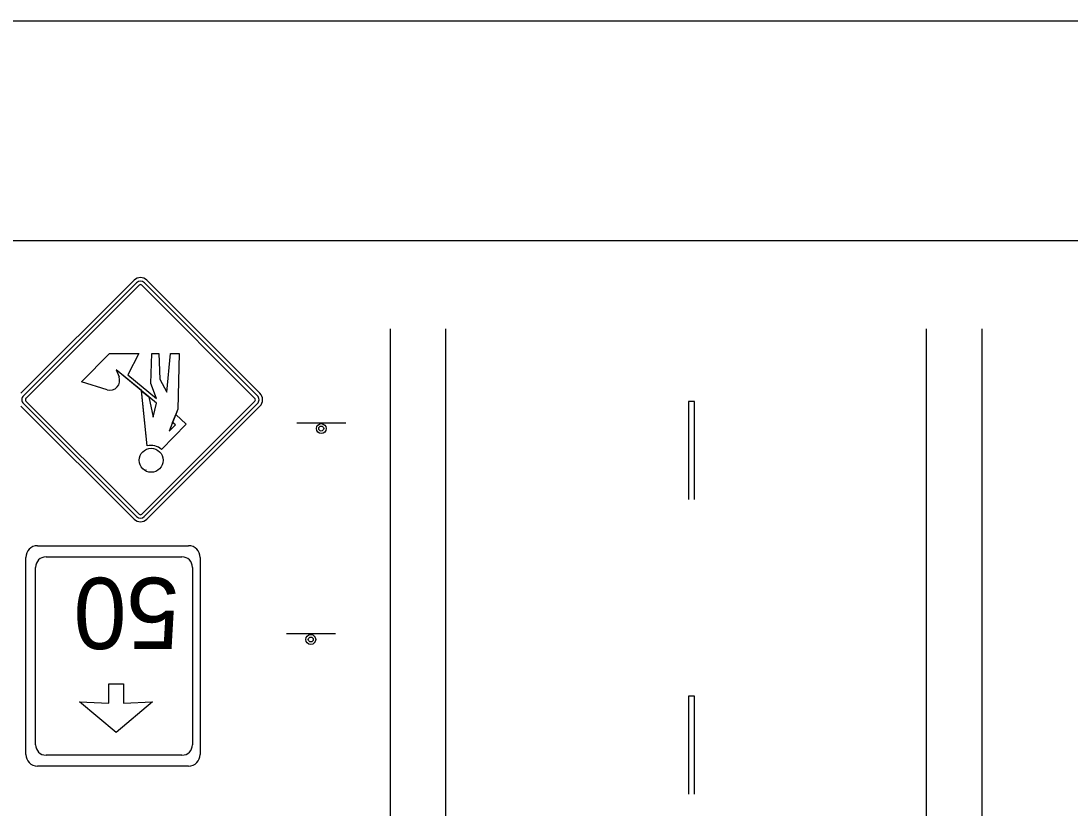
# Model space of a CAD drawing. Extents: x 2195 to 2411, y 202 to 481.
# Drawn here: x 2247.9 to 2299.6, y 442.1 to 480.9 of the extents above; entities that cross this region are included whole.
import ezdxf

# ---------------------------------------------------------------- set-up
doc = ezdxf.new("R2010")
doc.units = 0
for name, color, linetype in [('Level 1', 7, 'Continuous'), ('Level 10', 7, 'Continuous'), ('Level 2', 7, 'Continuous'), ('Level 44', 7, 'Continuous'), ('Level 60', 7, 'Continuous')]:
    doc.layers.add(name, color=color, linetype=linetype)

msp = doc.modelspace()

# ---------------------------------------------------------------- linework, layer by layer
at = {"layer": 'Level 1'}
for p, q in [((2253.464, 468.113), (2247.886, 462.542)), ((2259.668, 462.538), (2254.094, 468.113)), ((2253.587, 467.989), (2248.01, 462.418)), ((2253.711, 467.864), (2248.134, 462.293)), ((2259.42, 462.29), (2253.845, 467.864)), ((2259.544, 462.414), (2253.97, 467.989)), ((2247.886, 461.912), (2253.46, 456.337)), ((2248.01, 462.034), (2253.584, 456.461)), ((2248.133, 462.158), (2253.708, 456.584)), ((2253.842, 456.584), (2259.42, 462.155)), ((2253.966, 456.46), (2259.544, 462.032)), ((2254.09, 456.335), (2259.668, 461.908)), ((2254.035, 458.778), (2254.05, 458.778))]:
    msp.add_line(p, q, dxfattribs=at)
for points in [[(2252.142, 462.716), (2250.862, 463.098), (2252.246, 464.497), (2253.703, 464.497), (2253.157, 463.442), (2254.571, 462.284), (2254.294, 463.022), (2254.33, 464.497), (2254.677, 464.497), (2254.74, 463.237), (2255.08, 462.594), (2255.258, 464.497), (2255.685, 464.497), (2255.627, 461.764), (2255.188, 460.668), (2255.497, 460.985)], [(2252.142, 462.716), (2250.862, 463.098), (2252.246, 464.497), (2253.703, 464.497), (2253.157, 463.442), (2254.571, 462.284), (2254.294, 463.022), (2254.33, 464.497), (2254.677, 464.497), (2254.74, 463.237), (2255.08, 462.594), (2255.258, 464.497), (2255.685, 464.497), (2255.627, 461.764), (2255.188, 460.668), (2255.497, 460.985)], [(2252.142, 462.716), (2250.862, 463.098), (2252.246, 464.497), (2253.703, 464.497), (2253.157, 463.442), (2254.571, 462.284), (2254.294, 463.022), (2254.33, 464.497), (2254.677, 464.497), (2254.74, 463.237), (2255.08, 462.594)], [(2255.08, 462.594), (2255.258, 464.497), (2255.685, 464.497), (2255.627, 461.764), (2255.522, 461.501), (2256.028, 461.023), (2254.812, 459.768)], [(2254.115, 459.946), (2253.833, 462.666), (2254.196, 462.367), (2254.402, 461.354), (2254.57, 462.059), (2252.584, 463.697), (2252.721, 463.343)], [(2254.115, 459.946), (2253.833, 462.666), (2254.196, 462.367), (2254.402, 461.354), (2254.57, 462.059), (2252.584, 463.697), (2252.721, 463.343)], [(2254.115, 459.946), (2253.833, 462.668), (2252.584, 463.697), (2252.721, 463.343)], [(2255.497, 460.985), (2255.362, 461.098), (2255.523, 461.501), (2256.028, 461.023), (2254.812, 459.768)], [(2255.497, 460.985), (2255.362, 461.098), (2255.523, 461.501), (2256.028, 461.023), (2254.812, 459.768)]]:
    msp.add_lwpolyline(points, dxfattribs=at)
for points in [[(2254.196, 462.369), (2254.402, 461.354), (2254.57, 462.059)], [(2255.497, 460.985), (2255.361, 461.098), (2255.188, 460.668)]]:
    msp.add_lwpolyline(points, close=True, dxfattribs=at)
msp.add_circle((2254.304, 459.237), 0.591, dxfattribs=at)
msp.add_circle((2254.304, 459.237), 0.591, dxfattribs=at)
msp.add_circle((2254.304, 459.237), 0.591, dxfattribs=at)
for centre, radius, start, end in [((2253.778, 467.797), 0.446, 45, 134.9652), ((2253.778, 467.797), 0.27, 45, 134.9652), ((2253.778, 467.797), 0.0948, 45, 134.9652), ((2252.278, 463.172), 0.475, 253.381, 21.0999), ((2252.278, 463.172), 0.475, 253.381, 21.0999), ((2252.278, 463.172), 0.475, 253.381, 21.0999), ((2248.2, 462.226), 0.27, 134.9651, 225), ((2259.353, 462.223), 0.446, 314.965, 45), ((2248.2, 462.226), 0.0948, 134.9651, 225), ((2259.353, 462.223), 0.0948, 314.965, 45), ((2259.353, 462.223), 0.27, 314.965, 45), ((2254.304, 459.237), 0.734, 46.3135, 104.9576), ((2254.304, 459.237), 0.734, 46.3135, 104.9576), ((2254.304, 459.237), 0.734, 46.3135, 104.9576), ((2253.775, 456.652), 0.446, 225, 314.9651), ((2253.775, 456.652), 0.27, 225, 314.9651), ((2253.775, 456.652), 0.0948, 225, 314.9651)]:
    msp.add_arc(centre, radius, start, end, dxfattribs=at)
at = {"layer": 'Level 10'}
for p, q in [((2266.085, 465.708), (2266.085, 217.702)), ((2268.811, 465.708), (2268.811, 217.702)), ((2292.52, 465.708), (2292.52, 447.884)), ((2295.265, 465.708), (2295.265, 447.884)), ((2292.52, 447.884), (2292.52, 311.49)), ((2295.265, 447.884), (2295.265, 217.702))]:
    msp.add_line(p, q, dxfattribs=at)
at = {"layer": 'Level 2'}
for p, q in [((2280.806, 462.136), (2280.806, 457.298)), ((2281.096, 462.136), (2280.806, 462.136)), ((2281.096, 457.298), (2281.096, 462.136)), ((2280.806, 447.622), (2280.806, 442.784)), ((2281.096, 447.622), (2280.806, 447.622)), ((2281.096, 442.784), (2281.096, 447.622))]:
    msp.add_line(p, q, dxfattribs=at)
at = {"layer": 'Level 44'}
for p, q in [((2263.905, 461.072), (2261.486, 461.072)), ((2248.701, 455.029), (2256.151, 455.029)), ((2248.126, 444.743), (2248.126, 454.452)), ((2249.12, 454.478), (2255.824, 454.478)), ((2256.724, 454.454), (2256.724, 454.452)), ((2256.724, 454.452), (2256.724, 444.743)), ((2248.602, 445.221), (2248.602, 453.96)), ((2256.341, 453.962), (2256.341, 453.96)), ((2256.341, 453.96), (2256.341, 445.221)), ((2263.39, 450.678), (2260.971, 450.678)), ((2255.824, 444.704), (2249.12, 444.704)), ((2256.151, 444.168), (2248.701, 444.168))]:
    msp.add_line(p, q, dxfattribs=at)
msp.add_lwpolyline([(2254.373, 447.343), (2252.574, 445.828), (2250.776, 447.343), (2252.215, 447.266), (2252.215, 448.225), (2252.934, 448.225), (2252.934, 447.266)], close=True, dxfattribs=at)
for centre, radius in [((2262.691, 460.801), 0.242), ((2262.691, 460.801), 0.121), ((2262.175, 450.407), 0.242), ((2262.175, 450.407), 0.121)]:
    msp.add_circle(centre, radius, dxfattribs=at)
for centre, radius, start, end in [((2248.701, 454.454), 0.575, 90, 180), ((2256.149, 454.454), 0.575, 360, 90), ((2249.121, 453.962), 0.517, 90, 180), ((2255.824, 453.962), 0.517, 360, 90), ((2249.121, 445.223), 0.517, 180, 270), ((2255.824, 445.223), 0.517, 270, 360), ((2248.701, 444.744), 0.575, 180, 270), ((2256.149, 444.744), 0.575, 270, 360)]:
    msp.add_arc(centre, radius, start, end, dxfattribs=at)
at = {"layer": 'Level 60'}
for points in [[(2195.401, 480.884), (2411.401, 480.884), (2411.401, 201.884), (2195.401, 201.884)], [(2214.527, 470.075), (2401.401, 470.075), (2401.401, 212.693), (2214.527, 212.693)]]:
    msp.add_lwpolyline(points, close=True, dxfattribs=at)

# ---------------------------------------------------------------- texts
at = {"layer": 'Level 44'}
msp.add_text('50', height=3.5124, rotation=180, dxfattribs=at).set_placement((2255.7, 453.45))

doc.saveas('drawing.dxf')
